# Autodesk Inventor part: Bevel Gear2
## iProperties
Created: 2008-07
Part Number: Bevel Gear2
Material: Steel, Mild
Document SubType Name: Modeling
Designer: tangg
Categories: <?xml version="1.0" encoding="UTF-16"?> <MemberInstance><Categories><FamilyTemplate><FamilyTemplateParameter ValueType="xs:double" Id="1" ObjectReferenceKey="da
Mass: 60.2079 g
Surface Area: 39.179 cm^2
Volume: 7.66003 cm^3
Density: 7.86 g/cm^3
CustomPartVersion: 1
Author: tangg
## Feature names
1. Teeth Body [Revolution]
2. Loft
3. Circular Pattern
4. Loft Right
5. Circular Pattern Right
6. Loft Left
7. Circular Pattern Left
8. Fix Body [Revolution]
9. Bohrung1 [Hole]
